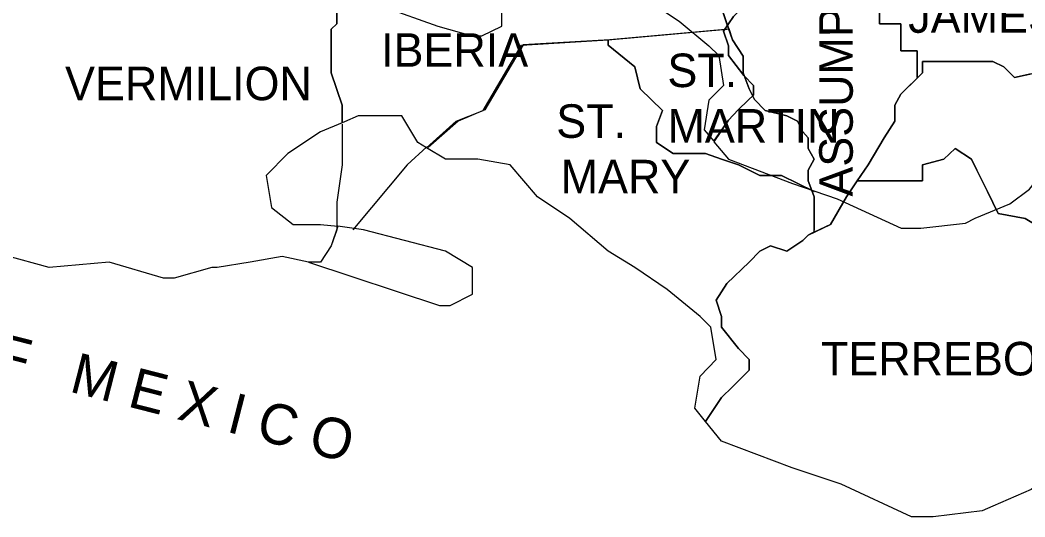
# Model space of a CAD drawing. Extents: x 0.19 to 2.82, y 0.04 to 1.79.
# Drawn here: x 2.3093 to 2.4634, y 1.3773 to 1.4536 of the extents above; entities that cross this region are included whole.
import ezdxf

# ---------------------------------------------------------------- set-up
doc = ezdxf.new("R2010")
doc.units = 0
for name, color, linetype in [('Dist02', 7, 'Continuous'), ('Dist03', 7, 'Continuous'), ('Standard Info', 7, 'Continuous')]:
    doc.layers.add(name, color=color, linetype=linetype)

msp = doc.modelspace()

# ---------------------------------------------------------------- linework, layer by layer
at = {"layer": 'Dist02'}
for points in [[(2.4369, 1.4685), (2.4354, 1.46625), (2.43315, 1.4625), (2.43007, 1.461), (2.42932, 1.46025), (2.42707, 1.45875), (2.42482, 1.45942), (2.42332, 1.45875), (2.42182, 1.45725), (2.41874, 1.45417), (2.41724, 1.45192), (2.41799, 1.44967), (2.41799, 1.44817), (2.42032, 1.44508), (2.42182, 1.44358), (2.42182, 1.44208), (2.42099, 1.44133), (2.41949, 1.43983), (2.41799, 1.43825), (2.41574, 1.43492)], [(2.41574, 1.43492), (2.41799, 1.43225), (2.42782, 1.4285), (2.43465, 1.42617), (2.44449, 1.42167), (2.44749, 1.42167), (2.45432, 1.42242), (2.45582, 1.42317), (2.46115, 1.42542), (2.46415, 1.42767), (2.46715, 1.4315), (2.4709, 1.43375), (2.47699, 1.43825), (2.47924, 1.43825), (2.48424, 1.43633)]]:
    msp.add_lwpolyline(points, dxfattribs=at)
at = {"layer": 'Dist03'}
for points in [[(2.37682, 1.47317), (2.37949, 1.47158), (2.38399, 1.47158), (2.38849, 1.47083), (2.39232, 1.46625), (2.39682, 1.46325), (2.40215, 1.45875), (2.4059, 1.45642), (2.4104, 1.45342), (2.41499, 1.44967), (2.41649, 1.44817), (2.41724, 1.44358), (2.41499, 1.44133), (2.41424, 1.43675), (2.41574, 1.435)], [(2.36049, 1.45725), (2.36507, 1.45567), (2.3734, 1.45267), (2.37865, 1.45117), (2.38015, 1.45117), (2.38324, 1.45267), (2.38324, 1.45642), (2.37949, 1.45875), (2.3764, 1.45942), (2.36807, 1.46175), (2.36482, 1.46217)], [(2.41574, 1.435), (2.41799, 1.43825), (2.41949, 1.43983), (2.42099, 1.44133), (2.42182, 1.44208), (2.42182, 1.44358), (2.42032, 1.44508), (2.41799, 1.44817), (2.41799, 1.44967), (2.41724, 1.45192), (2.41874, 1.45417), (2.42182, 1.45725), (2.42332, 1.45875), (2.42482, 1.45942), (2.42707, 1.45875), (2.42932, 1.46025), (2.43007, 1.461), (2.43099, 1.46142)]]:
    msp.add_lwpolyline(points, dxfattribs=at)
at = {"layer": 'Standard Info'}
for p, q in [((2.35909, 1.43801), (2.35872, 1.43782)), ((2.43774, 1.42893), (2.43774, 1.42893)), ((2.43077, 1.42746), (2.43114, 1.42728)), ((2.43114, 1.42105), (2.43114, 1.42151))]:
    msp.add_line(p, q, dxfattribs=at)
for points in [[(2.44021, 1.46138), (2.43939, 1.45891), (2.44113, 1.45891), (2.44113, 1.45304), (2.44443, 1.45304), (2.44443, 1.44891), (2.4469, 1.44891), (2.4469, 1.44479)], [(2.4469, 1.44479), (2.4469, 1.44891), (2.44443, 1.44891), (2.44443, 1.45304), (2.44113, 1.45304), (2.44113, 1.45891), (2.43939, 1.45891), (2.44021, 1.46138)], [(2.35872, 1.43782), (2.35872, 1.44057), (2.35707, 1.44552), (2.35707, 1.45221), (2.3579, 1.45304), (2.3579, 1.45643), (2.35872, 1.45891), (2.35909, 1.46056)], [(2.40785, 1.46056), (2.41528, 1.46056), (2.41693, 1.45808), (2.41858, 1.45808), (2.41693, 1.45551), (2.41803, 1.45221)], [(2.35817, 1.45707), (2.3579, 1.45643), (2.3579, 1.45304), (2.35707, 1.45221), (2.35707, 1.44552), (2.35872, 1.44057), (2.35872, 1.43782)], [(2.43114, 1.42151), (2.43114, 1.42481), (2.43114, 1.42646), (2.43022, 1.42893), (2.43022, 1.43058), (2.43114, 1.43223), (2.43022, 1.43388), (2.43022, 1.43553), (2.4294, 1.43645), (2.42857, 1.4381), (2.42692, 1.43892), (2.42362, 1.43975), (2.42197, 1.4414), (2.42115, 1.44305), (2.42023, 1.44552), (2.42023, 1.44809), (2.41858, 1.45056), (2.41775, 1.45304), (2.41693, 1.45551), (2.41748, 1.45625)], [(2.41803, 1.45221), (2.39979, 1.45056), (2.3865, 1.44983), (2.38063, 1.43984), (2.3765, 1.4381), (2.37192, 1.43406)], [(2.39951, 1.45056), (2.41775, 1.45221)], [(2.41803, 1.45231), (2.41858, 1.45056), (2.42023, 1.44809), (2.42023, 1.44552), (2.42115, 1.44305), (2.42197, 1.4414), (2.42362, 1.43975), (2.42692, 1.43892), (2.42857, 1.4381), (2.4294, 1.43645), (2.43022, 1.43553), (2.43022, 1.43388), (2.43114, 1.43223), (2.43022, 1.43058), (2.43022, 1.42893), (2.43077, 1.42746)], [(2.37165, 1.43397), (2.37623, 1.4381), (2.38035, 1.43975), (2.38622, 1.44974), (2.39951, 1.45056)], [(2.39951, 1.45056), (2.39951, 1.44974), (2.40364, 1.44644), (2.40446, 1.44305), (2.40785, 1.43975), (2.40694, 1.43727), (2.40694, 1.4348), (2.4095, 1.43315), (2.41115, 1.43315), (2.41445, 1.43315), (2.41693, 1.43223), (2.4195, 1.43141), (2.42115, 1.43058), (2.4228, 1.42976), (2.4261, 1.42976), (2.43114, 1.42728)], [(2.43114, 1.42728), (2.4261, 1.42976), (2.4228, 1.42976), (2.42115, 1.43058), (2.4195, 1.43141), (2.41693, 1.43223), (2.41445, 1.43315), (2.41115, 1.43315), (2.4095, 1.43315), (2.40694, 1.4348), (2.40694, 1.43727), (2.40785, 1.43975), (2.40446, 1.44305), (2.40364, 1.44644), (2.39951, 1.44974), (2.39951, 1.45056)], [(2.43774, 1.42893), (2.43939, 1.43141), (2.44186, 1.43553), (2.44351, 1.4381), (2.44351, 1.44057), (2.44443, 1.44222), (2.44773, 1.44552), (2.44773, 1.44726), (2.45607, 1.44726), (2.45855, 1.44726), (2.4602, 1.44644), (2.46185, 1.44479), (2.46515, 1.44552), (2.46689, 1.44644), (2.46854, 1.44644), (2.46936, 1.44479), (2.47101, 1.44644), (2.47605, 1.44644)], [(2.46441, 1.44534), (2.46185, 1.44479), (2.4602, 1.44644), (2.45855, 1.44726), (2.45607, 1.44726), (2.44773, 1.44726), (2.44773, 1.44552), (2.4469, 1.4447)], [(2.4469, 1.4447), (2.44443, 1.44222), (2.44351, 1.44057), (2.44351, 1.4381), (2.44186, 1.43553), (2.43939, 1.43141), (2.43774, 1.42893), (2.43609, 1.42646), (2.43361, 1.42224), (2.43114, 1.42105)], [(2.3612, 1.43892), (2.35909, 1.43801)], [(2.3612, 1.43892), (2.35909, 1.43801)], [(2.37165, 1.43397), (2.37036, 1.4348), (2.36789, 1.43892), (2.3612, 1.43892)], [(2.37165, 1.43397), (2.37036, 1.4348), (2.36789, 1.43892), (2.3612, 1.43892)], [(2.35872, 1.43782), (2.35542, 1.43645), (2.35038, 1.43315), (2.34708, 1.42976), (2.3479, 1.42481), (2.3512, 1.42224), (2.35542, 1.42224), (2.35808, 1.42196)], [(2.35872, 1.43764), (2.35872, 1.43727), (2.35872, 1.43141), (2.3579, 1.42563), (2.3579, 1.42141), (2.35707, 1.41894), (2.35542, 1.41646), (2.35359, 1.41646)], [(2.37174, 1.43416), (2.36871, 1.43141), (2.36037, 1.42141)], [(2.41445, 1.39199), (2.4128, 1.39401), (2.41363, 1.39896), (2.4161, 1.40152), (2.41528, 1.40647), (2.41363, 1.40812), (2.40859, 1.41225), (2.40364, 1.41564), (2.39951, 1.41811), (2.39365, 1.42316), (2.3887, 1.42646), (2.38448, 1.43141), (2.37953, 1.43223), (2.37458, 1.43223), (2.37165, 1.43397)], [(2.43774, 1.42893), (2.44773, 1.42893), (2.44773, 1.43141), (2.45103, 1.43223), (2.45277, 1.43388), (2.45525, 1.43223), (2.45607, 1.43058), (2.45772, 1.42728), (2.45937, 1.42389), (2.4635, 1.42316), (2.46771, 1.42059), (2.46689, 1.41811), (2.46936, 1.41646), (2.47184, 1.41399), (2.47349, 1.41316), (2.47605, 1.40977), (2.47853, 1.4073), (2.48183, 1.404), (2.4843, 1.40152), (2.48605, 1.39731), (2.4898, 1.39346)], [(2.4898, 1.39346), (2.48605, 1.39731), (2.4843, 1.40152), (2.48183, 1.404), (2.47853, 1.4073), (2.47605, 1.40977), (2.47349, 1.41316), (2.47184, 1.41399), (2.46936, 1.41646), (2.46689, 1.41811), (2.46771, 1.42059), (2.4635, 1.42316), (2.45937, 1.42389), (2.45772, 1.42728), (2.45607, 1.43058), (2.45525, 1.43223), (2.45277, 1.43388), (2.45103, 1.43223), (2.44773, 1.43141), (2.44773, 1.42893), (2.43774, 1.42893)], [(2.41445, 1.39199), (2.41693, 1.39566), (2.41858, 1.39731), (2.42023, 1.39896), (2.42115, 1.39987), (2.42115, 1.40152), (2.4195, 1.40317), (2.41693, 1.40647), (2.41693, 1.40812), (2.4161, 1.4106), (2.41775, 1.41316), (2.42115, 1.41646), (2.4228, 1.41811), (2.42445, 1.41894), (2.42692, 1.41811), (2.4294, 1.41976), (2.43022, 1.42059), (2.43361, 1.42224), (2.43609, 1.42646), (2.43774, 1.42893)], [(2.43086, 1.42719), (2.43114, 1.42646), (2.43114, 1.42481), (2.43114, 1.42316), (2.43114, 1.42141)], [(2.35359, 1.41646), (2.37366, 1.40977), (2.37531, 1.40977), (2.3787, 1.41151), (2.3787, 1.41564), (2.37458, 1.41811), (2.36202, 1.42141), (2.35808, 1.42196)], [(2.35808, 1.42196), (2.35707, 1.41894), (2.35542, 1.41646), (2.3546, 1.41646)], [(2.43123, 1.42114), (2.43022, 1.42059), (2.4294, 1.41976), (2.42692, 1.41811), (2.42445, 1.41894), (2.4228, 1.41811), (2.42115, 1.41646), (2.41775, 1.41316), (2.4161, 1.4106), (2.41693, 1.40812), (2.41693, 1.40647), (2.4195, 1.40317), (2.42115, 1.40152), (2.42115, 1.39987), (2.42023, 1.39896), (2.41858, 1.39731), (2.41693, 1.39566), (2.41445, 1.39199)], [(2.33956, 1.41564), (2.33874, 1.41564), (2.33296, 1.41399), (2.33131, 1.41399), (2.32297, 1.41646), (2.3138, 1.41564), (2.30711, 1.41747)], [(2.35359, 1.41646), (2.34955, 1.41729), (2.3446, 1.41646), (2.33956, 1.41564)], [(2.4898, 1.39346), (2.4843, 1.39566), (2.48183, 1.39566), (2.47514, 1.39061), (2.47101, 1.38814), (2.46771, 1.38401), (2.46441, 1.38154), (2.45855, 1.37897), (2.4569, 1.37824), (2.44938, 1.37732), (2.44608, 1.37732), (2.43526, 1.38236), (2.42775, 1.38484), (2.41693, 1.38896), (2.41445, 1.39199)]]:
    msp.add_lwpolyline(points, dxfattribs=at)

# ---------------------------------------------------------------- texts
for s, height, rotation, p in [('ASSUMPTION', 0.005147, 90.01, (2.43705, 1.42651)), ('G U L F   O F   M E X I C O', 0.0062, 345.6507, (2.26182, 1.41065))]:
    msp.add_text(s, height=height, rotation=rotation, dxfattribs=at).set_placement(p)
for s, height, p in [('JAMES', 0.005147, (2.44556, 1.45166)), ('IBERIA', 0.005147, (2.3647, 1.44644)), ('ST.', 0.005147, (2.40862, 1.44332)), ('VERMILION', 0.005146, (2.31623, 1.44131)), ('ST.', 0.005147, (2.39157, 1.43553)), ('MARTIN', 0.005147, (2.40863, 1.4348)), ('MARY', 0.005147, (2.39225, 1.42701)), ('TERREBONNE', 0.005147, (2.43216, 1.39905))]:
    msp.add_text(s, height=height, dxfattribs=at).set_placement(p)

doc.saveas('drawing.dxf')
